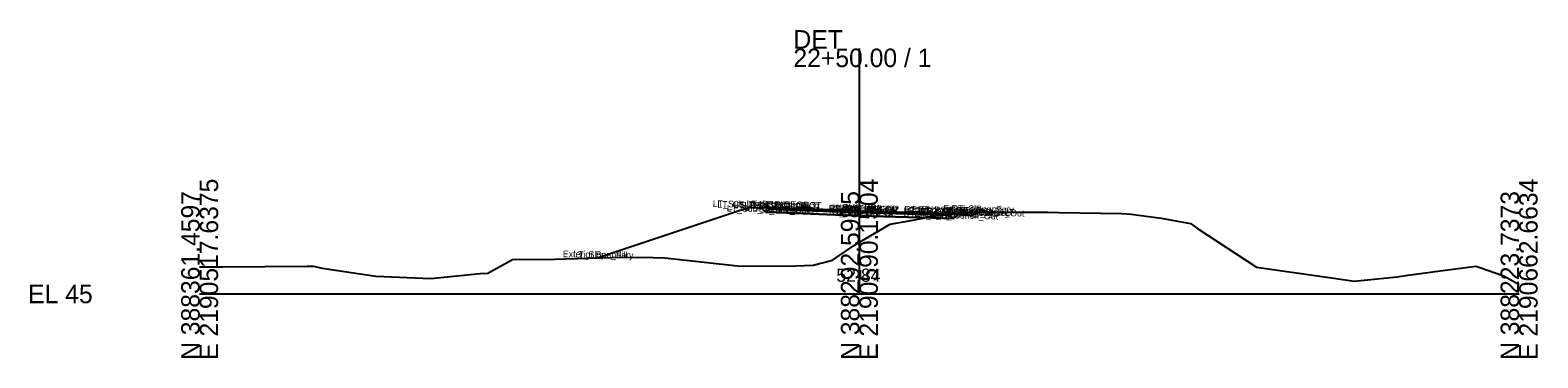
# Model space of a CAD drawing. Extents: x -26 to 1203, y -10 to 9543.
# Drawn here: x 974.3 to 1202.8, y 2490.3 to 2540 of the extents above; entities that cross this region are included whole.
import ezdxf

# ---------------------------------------------------------------- set-up
doc = ezdxf.new("R2010")
doc.units = 0
for name, color, linetype in [('Default', 7, 'Continuous'), ('Exist Cross Section Cell', 7, 'Continuous'), ('Exist XS Center Line Elevation Label', 7, 'Continuous'), ('Exist XS Ground Line', 7, 'Continuous'), ('Prop CMT Pvmt Course 1', 7, 'Continuous'), ('Prop CMT Pvmt Course 2', 7, 'Continuous'), ('Prop CMT Pvmt Course 3', 7, 'Continuous'), ('Prop CMT Pvmt Surface', 7, 'Continuous'), ('Prop CMT Pvmt Surface Shoulder', 7, 'Continuous'), ('Prop CMT Shld Paved Course 1', 7, 'Continuous'), ('Prop CMT Shld Paved Course 2', 7, 'Continuous'), ('Prop CMT Shld Paved Course 3', 7, 'Continuous'), ('Prop CMT Slope Grass', 7, 'Continuous'), ('Prop CMT Subgrade Earthwork', 7, 'Continuous'), ('Scratch_Level_0', 7, 'Continuous')]:
    doc.layers.add(name, color=color, linetype=linetype)

msp = doc.modelspace()

# ---------------------------------------------------------------- linework, layer by layer
at = {"layer": 'Exist Cross Section Cell'}
for p, q in [((1100, 2500), (1100, 2537.21)), ((1000, 2500), (1100, 2500)), ((1100, 2500), (1200, 2500))]:
    msp.add_line(p, q, dxfattribs=at)
at = {"layer": 'Exist XS Ground Line'}
for p, q in [((1107.54, 2511.11), (1111.8, 2511.89)), ((1111.8, 2511.89), (1114.44, 2512.13)), ((1114.44, 2512.13), (1115.38, 2512.23)), ((1115.38, 2512.23), (1115.92, 2512.32)), ((1115.92, 2512.32), (1116.66, 2512.36)), ((1116.66, 2512.36), (1117.59, 2512.4)), ((1117.59, 2512.4), (1127.66, 2512.4)), ((1127.66, 2512.4), (1128.62, 2512.4)), ((1128.62, 2512.4), (1130.23, 2512.37)), ((1130.23, 2512.37), (1139.73, 2512.22)), ((1139.73, 2512.22), (1140.54, 2512.16)), ((1140.54, 2512.16), (1141.2, 2512.11)), ((1141.2, 2512.11), (1145.73, 2511.48)), ((1100, 2507.84), (1104.66, 2510.6)), ((1104.66, 2510.6), (1107.54, 2511.11)), ((1145.73, 2511.48), (1150.18, 2510.71)), ((1150.18, 2510.71), (1151.27, 2509.95)), ((1151.27, 2509.95), (1160.17, 2504.04)), ((1095.95, 2505.12), (1099.13, 2507.32)), ((1099.13, 2507.32), (1100, 2507.84)), ((1043.7, 2503.13), (1047.44, 2505.25)), ((1047.44, 2505.25), (1053.84, 2505.29)), ((1053.84, 2505.29), (1064.19, 2505.58)), ((1064.19, 2505.58), (1068.75, 2505.54)), ((1068.75, 2505.54), (1070.51, 2505.49)), ((1070.51, 2505.49), (1081.99, 2504.22)), ((1092.99, 2504.37), (1095.95, 2505.12)), ((1000, 2504.09), (1001.78, 2504.11)), ((1001.78, 2504.11), (1002.65, 2504.13)), ((1002.65, 2504.13), (1003.47, 2504.13)), ((1003.47, 2504.13), (1016.3, 2504.19)), ((1016.3, 2504.19), (1017.27, 2504.19)), ((1017.27, 2504.19), (1018.58, 2503.93)), ((1018.58, 2503.93), (1026.7, 2502.7)), ((1026.7, 2502.7), (1035.04, 2502.34)), ((1035.04, 2502.34), (1042.51, 2503.08)), ((1042.51, 2503.08), (1043.7, 2503.13)), ((1081.99, 2504.22), (1090.37, 2504.29)), ((1090.37, 2504.29), (1092.99, 2504.37)), ((1160.17, 2504.04), (1171.56, 2502.44)), ((1171.56, 2502.44), (1175.01, 2501.93)), ((1175.01, 2501.93), (1181.5, 2502.61)), ((1181.5, 2502.61), (1182.77, 2502.78)), ((1182.77, 2502.78), (1188.05, 2503.51)), ((1188.05, 2503.51), (1193.49, 2504.22)), ((1193.49, 2504.22), (1194.04, 2503.99)), ((1194.04, 2503.99), (1197.7, 2502.75)), ((1197.7, 2502.75), (1200, 2501.44))]:
    msp.add_line(p, q, dxfattribs=at)
at = {"layer": 'Prop CMT Pvmt Course 1'}
for points in [[(1100, 2512.61), (1089, 2513.03)], [(1089, 2513.03), (1089, 2512.78)], [(1089, 2512.78), (1100, 2512.36)], [(1100, 2512.36), (1100, 2512.61)], [(1100, 2512.61), (1111, 2512.28)], [(1100, 2512.36), (1100, 2512.61)], [(1111, 2512.03), (1100, 2512.36)], [(1111, 2512.28), (1111, 2512.03)]]:
    msp.add_lwpolyline(points, dxfattribs=at)
msp.add_lwpolyline([(1100, 2512.36), (1100, 2512.48), (1100, 2512.48), (1100, 2512.36)], close=True, dxfattribs=at)
msp.add_lwpolyline([(1100, 2512.36), (1100, 2512.48), (1100, 2512.48), (1100, 2512.36)], close=True, dxfattribs=at)
at = {"layer": 'Prop CMT Pvmt Course 2'}
for points in [[(1089, 2512.78), (1100, 2512.36)], [(1100, 2512.36), (1089, 2512.78)], [(1089, 2512.78), (1089, 2512.78)], [(1100, 2512.36), (1100, 2512.36)], [(1111, 2512.03), (1100, 2512.36)], [(1100, 2512.36), (1100, 2512.36)], [(1100, 2512.36), (1111, 2512.03)], [(1111, 2512.03), (1111, 2512.03)]]:
    msp.add_lwpolyline(points, dxfattribs=at)
at = {"layer": 'Prop CMT Pvmt Course 3'}
for points in [[(1100, 2512.36), (1089, 2512.78)], [(1089, 2512.78), (1089, 2512.28)], [(1089, 2512.28), (1100, 2511.86)], [(1100, 2511.86), (1100, 2512.36)], [(1100, 2512.36), (1111, 2512.03)], [(1100, 2511.86), (1100, 2512.36)], [(1111, 2511.53), (1100, 2511.86)], [(1111, 2512.03), (1111, 2511.53)]]:
    msp.add_lwpolyline(points, dxfattribs=at)
at = {"layer": 'Prop CMT Pvmt Surface'}
for points in [[(1100, 2512.61), (1089, 2513.03)], [(1100, 2512.61), (1111, 2512.28)]]:
    msp.add_lwpolyline(points, dxfattribs=at)
at = {"layer": 'Prop CMT Pvmt Surface Shoulder'}
for points in [[(1089, 2513.03), (1087, 2513.1)], [(1111, 2512.28), (1113, 2512.22)]]:
    msp.add_lwpolyline(points, dxfattribs=at)
at = {"layer": 'Prop CMT Shld Paved Course 1'}
for points in [[(1089, 2513.03), (1087, 2513.1), (1086.76, 2512.86)], [(1086.76, 2512.86), (1089, 2512.78)], [(1089, 2512.78), (1089, 2513.03)], [(1111, 2512.28), (1113, 2512.22), (1113.26, 2511.96)], [(1111, 2512.03), (1111, 2512.28)], [(1113.26, 2511.96), (1111, 2512.03)]]:
    msp.add_lwpolyline(points, dxfattribs=at)
at = {"layer": 'Prop CMT Shld Paved Course 2'}
for points in [[(1089, 2512.78), (1086.76, 2512.86)], [(1086.76, 2512.86), (1086.76, 2512.86)], [(1086.76, 2512.86), (1089, 2512.78)], [(1089, 2512.78), (1089, 2512.78)], [(1111, 2512.03), (1113.26, 2511.96)], [(1113.26, 2511.96), (1111, 2512.03)], [(1111, 2512.03), (1111, 2512.03)], [(1113.26, 2511.96), (1113.26, 2511.96)]]:
    msp.add_lwpolyline(points, dxfattribs=at)
at = {"layer": 'Prop CMT Shld Paved Course 3'}
for points in [[(1089, 2512.78), (1086.76, 2512.86), (1086.26, 2512.88), (1085.78, 2512.4)], [(1085.78, 2512.4), (1089, 2512.28)], [(1089, 2512.28), (1089, 2512.78)], [(1111, 2512.03), (1113.26, 2511.96), (1113.76, 2511.94), (1114.27, 2511.43)], [(1111, 2511.53), (1111, 2512.03)], [(1114.27, 2511.43), (1111, 2511.53)]]:
    msp.add_lwpolyline(points, dxfattribs=at)
at = {"layer": 'Prop CMT Slope Grass'}
for points in [[(1087, 2513.1), (1083, 2513.01), (1060.38, 2505.47)], [(1113, 2512.22), (1117, 2511.9), (1117.01, 2511.89), (1118.03, 2512.4)]]:
    msp.add_lwpolyline(points, dxfattribs=at)
at = {"layer": 'Prop CMT Subgrade Earthwork'}
for points in [[(1085.78, 2512.4), (1085.12, 2513.06)], [(1089, 2512.28), (1085.78, 2512.4)], [(1100, 2511.86), (1089, 2512.28)], [(1100, 2511.86), (1111, 2511.53)], [(1114.27, 2511.43), (1114.91, 2512.06)], [(1111, 2511.53), (1114.27, 2511.43)]]:
    msp.add_lwpolyline(points, dxfattribs=at)

# ---------------------------------------------------------------- texts
at = {"layer": 'Default'}
msp.add_text('-', height=0.0001, dxfattribs=at).set_placement((1000, 2500))
at = {"layer": 'Exist Cross Section Cell'}
for s, p in [('DET', (1090, 2537.21)), ('22+50.00 / 1', (1090, 2534.41)), ('EL 45', (974, 2498.6))]:
    msp.add_text(s, height=2.8, dxfattribs=at).set_placement(p)
for s, p in [('E 2190517.6375', (1002.8, 2490)), ('E 2190590.1504', (1102.8, 2490)), ('E 2190662.6634', (1202.8, 2490)), ('N 388361.4597', (1000, 2490)), ('N 388292.5985', (1100, 2490)), ('N 388223.7373', (1200, 2490))]:
    msp.add_text(s, height=2.8, rotation=90, dxfattribs=at).set_placement(p)
at = {"layer": 'Exist XS Center Line Elevation Label'}
msp.add_text('52.84', height=2, dxfattribs=at).set_placement((1096.51, 2501.84))
at = {"layer": 'Scratch_Level_0'}
for s, p in [('LT_Sub_Trench_Out_DLT', (1077.77, 2513.2)), ('LT_GS_OS_CTL', (1078.46, 2513.1)), ('LT_PS3_Shelf_Out', (1080.92, 2512.98)), ('LT_PS3_OEOP', (1082.55, 2512.94)), ('LT_PS2_OEOP', (1082.55, 2512.94)), ('LT_PS1_OEOP', (1082.91, 2513.18)), ('LT_PV1_OEOT', (1084.87, 2513.11)), ('LT_Sub_Trench_Out', (1079.89, 2512.51)), ('LT_PV2_OEOT', (1084.75, 2512.86)), ('LT_PV3_OEOT', (1084.75, 2512.86)), ('LT_Sub_OEOT', (1084.77, 2512.36)), ('RT_PV2_OEEOP', (1095.33, 2512.45)), ('RT_PV3_OEEOP', (1095.33, 2512.45)), ('RT_Sub_OEEOP', (1095.36, 2511.95)), ('LT_PV2_OEEOP', (1095.39, 2512.45)), ('LT_PV3_OEEOP', (1095.39, 2512.45)), ('LT_Sub_OEEOP', (1095.42, 2511.95)), ('RT_PV1_OEEOP', (1095.45, 2512.57)), ('LT_PV1_OEEOP', (1095.51, 2512.57)), ('RT_PV2_IEEOP', (1095.71, 2512.44)), ('LT_PV2_IEEOP', (1095.77, 2512.44)), ('RT_PV1_IEEOP', (1095.83, 2512.56)), ('LT_PV1_IEEOP', (1095.89, 2512.56)), ('PV2_PGL', (1097.35, 2512.41)), ('PV1_PGL', (1097.47, 2512.66)), ('RT_PV3_OEOT', (1106.69, 2512.11)), ('RT_PV2_OEOT', (1106.69, 2512.11)), ('RT_Sub_OEOT', (1106.71, 2511.61)), ('RT_PV1_OEOT', (1106.81, 2512.36)), ('RT_Sub_Trench_Out_DLT', (1107.5, 2512.21)), ('RT_Sub_Trench_Out', (1108.32, 2511.54)), ('RT_PS3_Shelf_Out', (1108.36, 2512.05)), ('RT_PS1_OEOP', (1108.85, 2512.3)), ('RT_PS3_OEOP', (1108.99, 2512.04)), ('RT_PS2_OEOP', (1108.99, 2512.04)), ('RT_SS_Ditch_Base_Out', (1110.21, 2512.03)), ('RT_GS_OS_CTL', (1112.41, 2511.99)), ('Exterior Boundary', (1112.69, 2512.51)), ('RT_Slope_Cut', (1113.97, 2512.48)), ('Exterior Boundary', (1055.04, 2505.58)), ('LT_Slope_Fill', (1056.62, 2505.55))]:
    msp.add_text(s, height=1, rotation=358.8836, dxfattribs=at).set_placement(p)

doc.saveas('drawing.dxf')
